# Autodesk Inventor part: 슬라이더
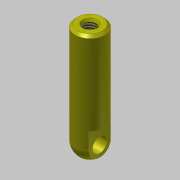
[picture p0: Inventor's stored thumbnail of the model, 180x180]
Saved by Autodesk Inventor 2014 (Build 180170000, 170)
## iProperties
Created: 2016-08
Part Number: 슬라이더
Material: 강철, 탄소
Document SubType Name: Modeling
Designer: mduedu
Density: 7.87 g/cm^3
Appearance: 노란색
Author: mduedu
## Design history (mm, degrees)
sketch "스케치1"
  geometry: C1 r 6 at (0, 0); 1 further point
  constraints: 1 centre point, 1 coincident
  dimensions: "d0" = 12 diameter of C1
extrude "돌출1" new body sketch "스케치1" distance "d1" = 47; taper "d2" = 0 deg
fillet "모깎기1" dims "d21" = 6
sketch "스케치6"
  geometry: L1 (6, 6)-(6, 47) reference; L2 (-6, 6)-(-6, 47) reference; L3 (6, 47)-(-6, 47) reference; L4 (0, 47)-(0, 0); L5 (6, 13)-(4, 13); L6 (4, 13)-(4, 0); L7 (4, 0)-(6, 0); L8 (6, 0)-(6, 13); L9 (-6, 13)-(-4, 13); L10 (-4, 13)-(-4, 0); L11 (-4, 0)-(-6, 0); L12 (-6, 0)-(-6, 13)
  constraints: 18 end point, 4 symmetric about line, 2 parallel, 2 perpendicular, 1 horizontal, 1 horizontal alignment, 1 midpoint, 1 point on line
  dimensions: "d22" = 13 distance of L7.end L5.start; "d24" = 4 distance between parallel lines of L6 L4
extrude "돌출5" cut sketch "스케치6" stored distance "d25" = 8; taper "d26" = 0 deg
sketch "스케치8"
  geometry: C1 r 3 at (6, 0); 1 further point
  constraints: 1 centre point, 1 horizontal alignment
  dimensions: "d27" = 6 diameter of C1; "d28" = 6 distance of point (0, 0) C1.centre
extrude "돌출6" cut sketch "스케치8" stored distance "d29" = 8; taper "d30" = 0 deg
hole "구멍1" diameter "d33" = 4.917; stored, may be unused: countersink angle "d37" = 90 deg, drill point angle "d39" = 118 deg; dims "d31" = 10, "d32" = 10, "d34" = 10, "d35" = 4, "d36" = 2, "d38" = 12
chamfer "모따기1" distance "d40" = 1; stored, may be unused: second distance "d41" = 2, angle "d42" = 30 deg
chamfer "모따기2" distance "d43" = 1; stored, may be unused: second distance "d44" = 2, angle "d45" = 30 deg
node "솔리드1"
